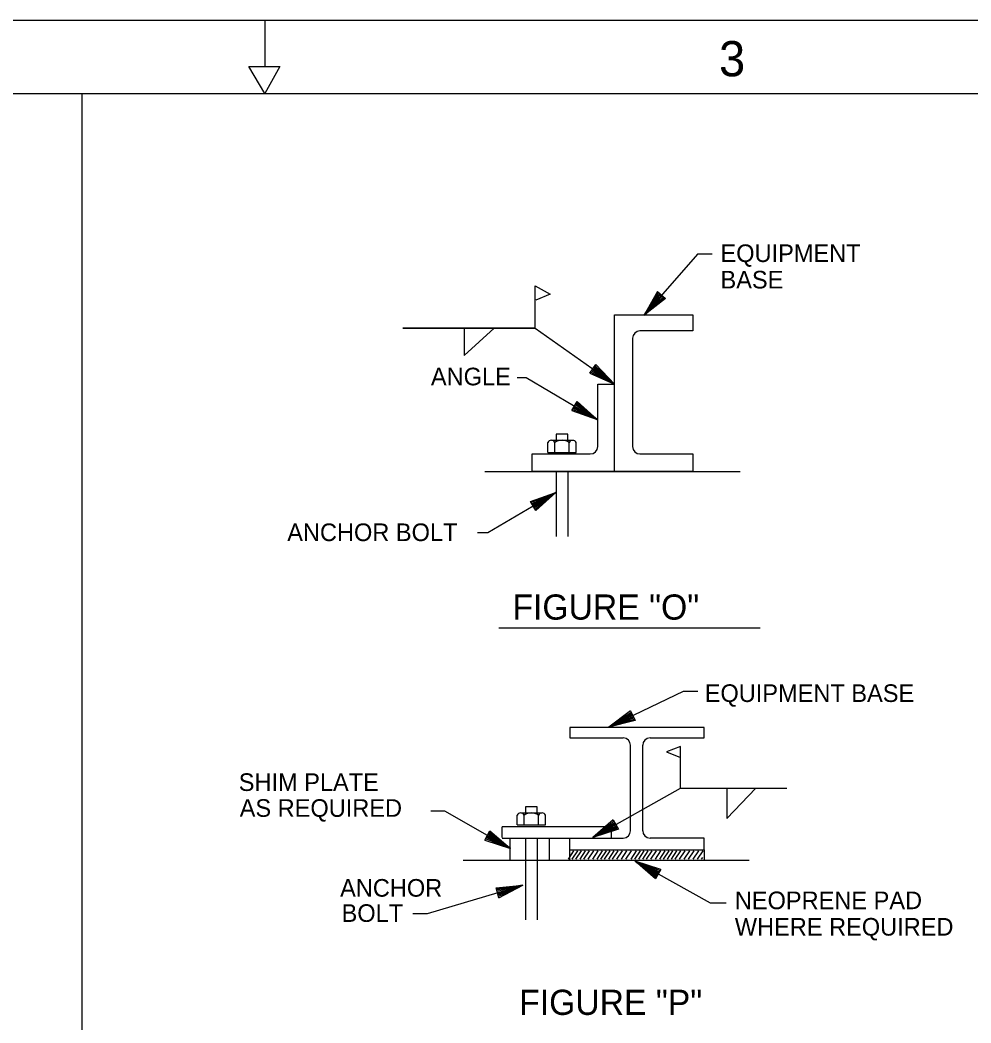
# Model space of a CAD drawing. Extents: x 9999.96 to 10005.26, y 9999.88 to 10002.38.
# Drawn here: x 10001.613 to 10002.153, y 10001.815 to 10002.385 of the extents above; entities that cross this region are included whole.
import ezdxf

# ---------------------------------------------------------------- set-up
doc = ezdxf.new("R2010")
doc.units = 0
doc.layers.add('Level 1', color=7, linetype='Continuous')
doc.layers.add('Level 2', color=7, linetype='Continuous')

msp = doc.modelspace()

# ---------------------------------------------------------------- linework, layer by layer
at = {"layer": 'Level 1'}
for p, q in [((9999.96033, 10002.38453), (10003.46033, 10002.38453)), ((10001.752, 10002.38453), (10001.752, 10002.35811)), ((10001.74308, 10002.35811), (10001.76067, 10002.35811)), ((10001.752, 10002.34286), (10001.74308, 10002.35811)), ((10001.76067, 10002.35811), (10001.752, 10002.34286)), ((10000.127, 10002.34286), (10003.41867, 10002.34286))]:
    msp.add_line(p, q, dxfattribs=at)
at = {"layer": 'Level 2'}
for p, q in [((10001.64817, 10002.34286), (10001.64817, 9999.9262)), ((10001.90547, 10002.20957), (10001.90547, 10002.23365)), ((10001.90547, 10002.23365), (10001.91399, 10002.22891)), ((10001.97499, 10002.2304), (10001.9673, 10002.21711)), ((10001.97499, 10002.2304), (10001.9673, 10002.21711)), ((10001.9673, 10002.21711), (10001.97557, 10002.2299)), ((10001.9673, 10002.21711), (10001.97557, 10002.2299)), ((10001.9673, 10002.21711), (10001.97622, 10002.22935)), ((10001.9673, 10002.21711), (10001.97622, 10002.22935)), ((10001.97499, 10002.2304), (10001.97951, 10002.22642)), ((10001.97499, 10002.2304), (10001.97951, 10002.22642)), ((10001.91399, 10002.22891), (10001.90595, 10002.22559)), ((10001.9673, 10002.21711), (10001.97671, 10002.2289)), ((10001.9673, 10002.21711), (10001.97671, 10002.2289)), ((10001.97724, 10002.22844), (10001.9673, 10002.21711)), ((10001.97724, 10002.22844), (10001.9673, 10002.21711)), ((10001.9673, 10002.21711), (10001.9778, 10002.22793)), ((10001.9673, 10002.21711), (10001.9778, 10002.22793)), ((10001.9673, 10002.21711), (10001.97836, 10002.22745)), ((10001.9673, 10002.21711), (10001.97836, 10002.22745)), ((10001.9673, 10002.21711), (10001.97891, 10002.22696)), ((10001.9673, 10002.21711), (10001.97891, 10002.22696)), ((10001.97951, 10002.22642), (10001.9673, 10002.21711)), ((10001.97951, 10002.22642), (10001.9673, 10002.21711)), ((10001.95049, 10002.12836), (10001.95049, 10002.21717)), ((10001.95049, 10002.21717), (10001.9949, 10002.21717)), ((10001.9949, 10002.21717), (10001.9949, 10002.20805)), ((10001.90547, 10002.20957), (10001.83046, 10002.20957)), ((10001.8652, 10002.20957), (10001.8652, 10002.19418)), ((10001.8652, 10002.19418), (10001.88218, 10002.20957)), ((10001.90547, 10002.20957), (10001.90547, 10002.20957)), ((10001.9949, 10002.20805), (10001.96496, 10002.20805)), ((10001.96079, 10002.20389), (10001.96079, 10002.14244)), ((10001.93645, 10002.18413), (10001.93993, 10002.18904)), ((10001.93645, 10002.18413), (10001.95049, 10002.17792)), ((10001.95049, 10002.17792), (10001.93689, 10002.18475)), ((10001.95049, 10002.17792), (10001.93735, 10002.18545)), ((10001.95049, 10002.17792), (10001.93776, 10002.18598)), ((10001.93816, 10002.18656), (10001.95049, 10002.17792)), ((10001.95049, 10002.17792), (10001.93859, 10002.18718)), ((10001.95049, 10002.17792), (10001.93902, 10002.18779)), ((10001.95049, 10002.17792), (10001.93944, 10002.18838)), ((10001.93993, 10002.18904), (10001.95049, 10002.17792)), ((10001.94097, 10002.14244), (10001.94097, 10002.17792)), ((10001.94097, 10002.17792), (10001.95049, 10002.17792)), ((10001.92625, 10002.16283), (10001.92931, 10002.16802)), ((10001.94074, 10002.15777), (10001.92851, 10002.1667)), ((10001.94074, 10002.15777), (10001.9289, 10002.16731)), ((10001.92931, 10002.16802), (10001.94074, 10002.15777)), ((10001.92625, 10002.16283), (10001.94074, 10002.15777)), ((10001.94074, 10002.15777), (10001.92664, 10002.16349)), ((10001.94074, 10002.15777), (10001.92704, 10002.16423)), ((10001.94074, 10002.15777), (10001.92741, 10002.16479)), ((10001.92775, 10002.16541), (10001.94074, 10002.15777)), ((10001.94074, 10002.15777), (10001.92815, 10002.16605)), ((10001.91269, 10002.13916), (10001.91269, 10002.14477)), ((10001.91472, 10002.14599), (10001.92678, 10002.14599)), ((10001.91669, 10002.13916), (10001.91669, 10002.14477)), ((10001.92478, 10002.13916), (10001.92478, 10002.14477)), ((10001.9288, 10002.13916), (10001.9288, 10002.14472)), ((10001.90371, 10002.12836), (10001.90371, 10002.13827)), ((10001.90371, 10002.13827), (10001.9368, 10002.13827)), ((10001.91269, 10002.13916), (10001.9288, 10002.13916)), ((10001.96496, 10002.13827), (10001.9949, 10002.13827)), ((10001.9949, 10002.13827), (10001.9949, 10002.12836)), ((10001.87689, 10002.12836), (10002.02185, 10002.12836)), ((10001.9949, 10002.12836), (10001.90371, 10002.12836)), ((10001.91745, 10002.12836), (10001.91745, 10002.0914)), ((10001.92406, 10002.12836), (10001.92406, 10002.0914)), ((10001.90277, 10002.11133), (10001.91727, 10002.11636)), ((10001.91727, 10002.11636), (10001.90318, 10002.11063)), ((10001.91727, 10002.11636), (10001.90354, 10002.10999)), ((10001.91727, 10002.11636), (10001.90393, 10002.10935)), ((10001.9043, 10002.1087), (10001.91727, 10002.11636)), ((10001.91727, 10002.11636), (10001.90467, 10002.10809)), ((10001.91727, 10002.11636), (10001.90499, 10002.10751)), ((10001.91727, 10002.11636), (10001.90544, 10002.10679)), ((10001.90582, 10002.10614), (10001.91727, 10002.11636)), ((10001.90582, 10002.10614), (10001.90277, 10002.11133)), ((10001.88491, 10002.03946), (10002.03314, 10002.03946)), ((10001.95958, 10001.99241), (10001.9473, 10001.9832)), ((10001.9473, 10001.9832), (10001.95992, 10001.99172)), ((10001.9473, 10001.9832), (10001.9603, 10001.99097)), ((10001.9473, 10001.9832), (10001.96056, 10001.99035)), ((10001.95958, 10001.99241), (10001.96218, 10001.98697)), ((10001.96089, 10001.98973), (10001.9473, 10001.9832)), ((10001.9473, 10001.9832), (10001.9612, 10001.98904)), ((10001.9473, 10001.9832), (10001.96153, 10001.98838)), ((10001.9473, 10001.9832), (10001.96183, 10001.98772)), ((10001.96218, 10001.98697), (10001.9473, 10001.9832)), ((10002.00135, 10001.98302), (10001.92524, 10001.98302)), ((10001.92524, 10001.98302), (10001.92524, 10001.97706)), ((10002.00135, 10001.97706), (10002.00135, 10001.98302)), ((10001.92524, 10001.97706), (10001.95545, 10001.97706)), ((10001.97072, 10001.97706), (10002.00135, 10001.97706)), ((10001.95961, 10001.9244), (10001.95961, 10001.9729)), ((10001.96655, 10001.9244), (10001.96655, 10001.9729)), ((10001.98805, 10001.97216), (10001.97996, 10001.96921)), ((10001.97996, 10001.96921), (10001.98805, 10001.9659)), ((10001.98805, 10001.9486), (10001.98805, 10001.97216)), ((10001.93822, 10001.92046), (10001.98805, 10001.9486)), ((10001.98805, 10001.9486), (10002.0484, 10001.9486)), ((10002.01418, 10001.9486), (10002.01418, 10001.93131)), ((10002.01418, 10001.93131), (10002.03073, 10001.9486)), ((10001.89526, 10001.92764), (10001.89526, 10001.93325)), ((10001.89729, 10001.93447), (10001.90935, 10001.93447)), ((10001.89926, 10001.92764), (10001.89926, 10001.93325)), ((10001.90735, 10001.92764), (10001.90735, 10001.93325)), ((10001.91138, 10001.92764), (10001.91138, 10001.9332)), ((10001.89526, 10001.92764), (10001.91138, 10001.92764)), ((10001.94985, 10001.93048), (10001.93822, 10001.92046)), ((10001.93822, 10001.92046), (10001.95023, 10001.92981)), ((10001.93822, 10001.92046), (10001.95066, 10001.92908)), ((10001.93822, 10001.92046), (10001.95097, 10001.92849)), ((10001.95132, 10001.92789), (10001.93822, 10001.92046)), ((10001.94985, 10001.93048), (10001.9528, 10001.92522)), ((10001.87685, 10001.9191), (10001.87985, 10001.92433)), ((10001.89142, 10001.91424), (10001.87871, 10001.92234)), ((10001.89142, 10001.91424), (10001.87907, 10001.923)), ((10001.89142, 10001.91424), (10001.87944, 10001.92363)), ((10001.87985, 10001.92433), (10001.89142, 10001.91424)), ((10001.94886, 10001.92657), (10001.88678, 10001.92657)), ((10001.88678, 10001.92049), (10001.88678, 10001.92657)), ((10001.93822, 10001.92046), (10001.95169, 10001.92722)), ((10001.93822, 10001.92046), (10001.95206, 10001.92658)), ((10001.93822, 10001.92046), (10001.95241, 10001.92595)), ((10001.9528, 10001.92522), (10001.93822, 10001.92046)), ((10001.94886, 10001.92049), (10001.94886, 10001.92657)), ((10001.87685, 10001.9191), (10001.89142, 10001.91424)), ((10001.89142, 10001.91424), (10001.87724, 10001.91977)), ((10001.89142, 10001.91424), (10001.87764, 10001.92051)), ((10001.89142, 10001.91424), (10001.87799, 10001.92108)), ((10001.87832, 10001.9217), (10001.89142, 10001.91424)), ((10001.88678, 10001.92023), (10001.95545, 10001.92023)), ((10001.8914, 10001.90765), (10001.8914, 10001.92023)), ((10001.90002, 10001.92023), (10001.90002, 10001.87382)), ((10001.90664, 10001.92023), (10001.90664, 10001.87382)), ((10001.91354, 10001.90765), (10001.91354, 10001.92023)), ((10001.92516, 10001.91354), (10001.92516, 10001.92023)), ((10002.00142, 10001.92023), (10001.97072, 10001.92023)), ((10002.00142, 10001.91354), (10002.00142, 10001.92023)), ((10001.92433, 10001.90833), (10001.9275, 10001.91295)), ((10001.92516, 10001.90765), (10001.92516, 10001.91354)), ((10001.92516, 10001.91354), (10002.00142, 10001.91354)), ((10001.92599, 10001.91074), (10001.9275, 10001.91295)), ((10001.92649, 10001.90833), (10001.92966, 10001.91295)), ((10001.92649, 10001.90833), (10001.92966, 10001.91295)), ((10001.92866, 10001.90833), (10001.93182, 10001.91295)), ((10001.92866, 10001.90833), (10001.93182, 10001.91295)), ((10001.93096, 10001.90833), (10001.93413, 10001.91295)), ((10001.93096, 10001.90833), (10001.93413, 10001.91295)), ((10001.93311, 10001.90833), (10001.93628, 10001.91295)), ((10001.93311, 10001.90833), (10001.93628, 10001.91295)), ((10001.93556, 10001.90833), (10001.93873, 10001.91295)), ((10001.93556, 10001.90833), (10001.93873, 10001.91295)), ((10001.93816, 10001.90833), (10001.94132, 10001.91295)), ((10001.93816, 10001.90833), (10001.94132, 10001.91295)), ((10001.94061, 10001.90833), (10001.94378, 10001.91295)), ((10001.94277, 10001.90833), (10001.94594, 10001.91295)), ((10001.94494, 10001.90833), (10001.9481, 10001.91295)), ((10001.94724, 10001.90833), (10001.95041, 10001.91295)), ((10001.9494, 10001.90833), (10001.95256, 10001.91295)), ((10001.95184, 10001.90833), (10001.95501, 10001.91295)), ((10001.95444, 10001.90833), (10001.9576, 10001.91295)), ((10001.95703, 10001.90833), (10001.9602, 10001.91295)), ((10001.95992, 10001.90833), (10001.96308, 10001.91295)), ((10001.96207, 10001.90833), (10001.96524, 10001.91295)), ((10001.96424, 10001.90833), (10001.96741, 10001.91295)), ((10001.96654, 10001.90833), (10001.96971, 10001.91295)), ((10001.9687, 10001.90833), (10001.97186, 10001.91295)), ((10001.97115, 10001.90833), (10001.97431, 10001.91295)), ((10001.97374, 10001.90833), (10001.97691, 10001.91295)), ((10001.9762, 10001.90833), (10001.97936, 10001.91295)), ((10001.97835, 10001.90833), (10001.98152, 10001.91295)), ((10001.98052, 10001.90833), (10001.98369, 10001.91295)), ((10001.98282, 10001.90833), (10001.98599, 10001.91295)), ((10001.98498, 10001.90833), (10001.98815, 10001.91295)), ((10001.98743, 10001.90833), (10001.99059, 10001.91295)), ((10001.99002, 10001.90833), (10001.99319, 10001.91295)), ((10001.99261, 10001.90833), (10001.99578, 10001.91295)), ((10001.99521, 10001.90833), (10001.99838, 10001.91295)), ((10001.99766, 10001.90833), (10002.00082, 10001.91295)), ((10002.00142, 10001.91354), (10002.00142, 10001.90765)), ((10001.86463, 10001.90765), (10002.02697, 10001.90765)), ((10001.97534, 10001.89981), (10001.96217, 10001.9071)), ((10001.97385, 10001.89716), (10001.96217, 10001.9071)), ((10001.97678, 10001.90242), (10001.96217, 10001.9071)), ((10001.96217, 10001.9071), (10001.97461, 10001.8985)), ((10001.96217, 10001.9071), (10001.97602, 10001.901)), ((10001.96217, 10001.9071), (10001.97426, 10001.89786)), ((10001.96217, 10001.9071), (10001.97497, 10001.89916)), ((10001.96217, 10001.9071), (10001.97568, 10001.90043)), ((10001.96217, 10001.9071), (10001.97642, 10001.90175)), ((10001.99996, 10001.90833), (10002.00061, 10001.90928)), ((10001.97678, 10001.90242), (10001.97385, 10001.89716)), ((10001.88327, 10001.89205), (10001.89855, 10001.89344)), ((10001.89855, 10001.89344), (10001.88349, 10001.89127)), ((10001.89855, 10001.89344), (10001.88369, 10001.89057)), ((10001.89855, 10001.89344), (10001.88391, 10001.88985)), ((10001.88411, 10001.88914), (10001.89855, 10001.89344)), ((10001.89855, 10001.89344), (10001.88432, 10001.88846)), ((10001.89855, 10001.89344), (10001.88449, 10001.88781)), ((10001.89855, 10001.89344), (10001.88475, 10001.88701)), ((10001.88497, 10001.88628), (10001.89855, 10001.89344)), ((10001.88497, 10001.88628), (10001.88327, 10001.89205))]:
    msp.add_line(p, q, dxfattribs=at)
for points in [[(10002.00595, 10002.25163), (10001.99767, 10002.25163), (10001.9673, 10002.21711)], [(10001.83046, 10002.20957), (10001.90547, 10002.20957), (10001.95049, 10002.17792)], [(10001.89519, 10002.18158), (10001.90036, 10002.18158), (10001.94074, 10002.15777)], [(10001.92406, 10002.14602), (10001.92406, 10002.14941), (10001.91745, 10002.14941), (10001.91745, 10002.14602)], [(10001.87276, 10002.09359), (10001.87863, 10002.09359), (10001.91727, 10002.11636)], [(10001.99783, 10002.00342), (10001.98951, 10002.00342), (10001.9473, 10001.9832)], [(10001.84624, 10001.93565), (10001.85397, 10001.93565), (10001.89142, 10001.91424)], [(10001.90664, 10001.9345), (10001.90664, 10001.93789), (10001.90002, 10001.93789), (10001.90002, 10001.9345)], [(10002.01389, 10001.88333), (10002.00497, 10001.88333), (10001.96217, 10001.9071)], [(10001.83614, 10001.87739), (10001.84446, 10001.87739), (10001.89855, 10001.89344)]]:
    msp.add_lwpolyline(points, dxfattribs=at)
for centre, radius, start, end in [((10001.96496, 10002.20389), 0.00417, 90, 180), ((10001.91469, 10002.14373), 0.00225, 27.8877, 152.0342), ((10001.92073, 10002.13854), 0.00744, 57.0062, 122.943), ((10001.92677, 10002.14372), 0.00225, 26.7827, 151.8391), ((10001.9368, 10002.14244), 0.00417, 270, 0), ((10001.96496, 10002.14244), 0.00417, 180, 270), ((10001.95545, 10001.9729), 0.00417, 0, 90), ((10001.97072, 10001.9729), 0.00417, 90, 180), ((10001.89726, 10001.93221), 0.00225, 27.8877, 152.0342), ((10001.9033, 10001.92702), 0.00744, 57.0062, 122.943), ((10001.90935, 10001.9322), 0.00225, 26.7827, 151.8391), ((10001.95545, 10001.9244), 0.00417, 270, 0), ((10001.97072, 10001.9244), 0.00417, 180, 270)]:
    msp.add_arc(centre, radius, start, end, dxfattribs=at)

# ---------------------------------------------------------------- texts
at = {"layer": 'Level 1'}
msp.add_text('3', height=0.02, dxfattribs=at).set_placement((10002.00983, 10002.35261))
at = {"layer": 'Level 2'}
for s, height, p in [('EQUIPMENT', 0.01, (10002.01068, 10002.24718)), ('BASE', 0.01, (10002.01068, 10002.23218)), ('ANGLE', 0.01, (10001.84633, 10002.1772)), ('ANCHOR BOLT', 0.01, (10001.76479, 10002.08879)), ('FIGURE "O"', 0.014301, (10001.89259, 10002.0442)), ('EQUIPMENT BASE', 0.01, (10002.00173, 10001.99747)), ('SHIM PLATE', 0.01, (10001.73727, 10001.94696)), ('AS REQUIRED', 0.01, (10001.73781, 10001.93228)), ('ANCHOR', 0.01, (10001.7948, 10001.88695)), ('NEOPRENE PAD', 0.01, (10002.01881, 10001.87986)), ('BOLT  ', 0.01, (10001.79564, 10001.87264)), ('WHERE REQUIRED', 0.01, (10002.01881, 10001.86486)), ('FIGURE "P"', 0.014301, (10001.89643, 10001.81984))]:
    msp.add_text(s, height=height, dxfattribs=at).set_placement(p)

doc.saveas('drawing.dxf')
